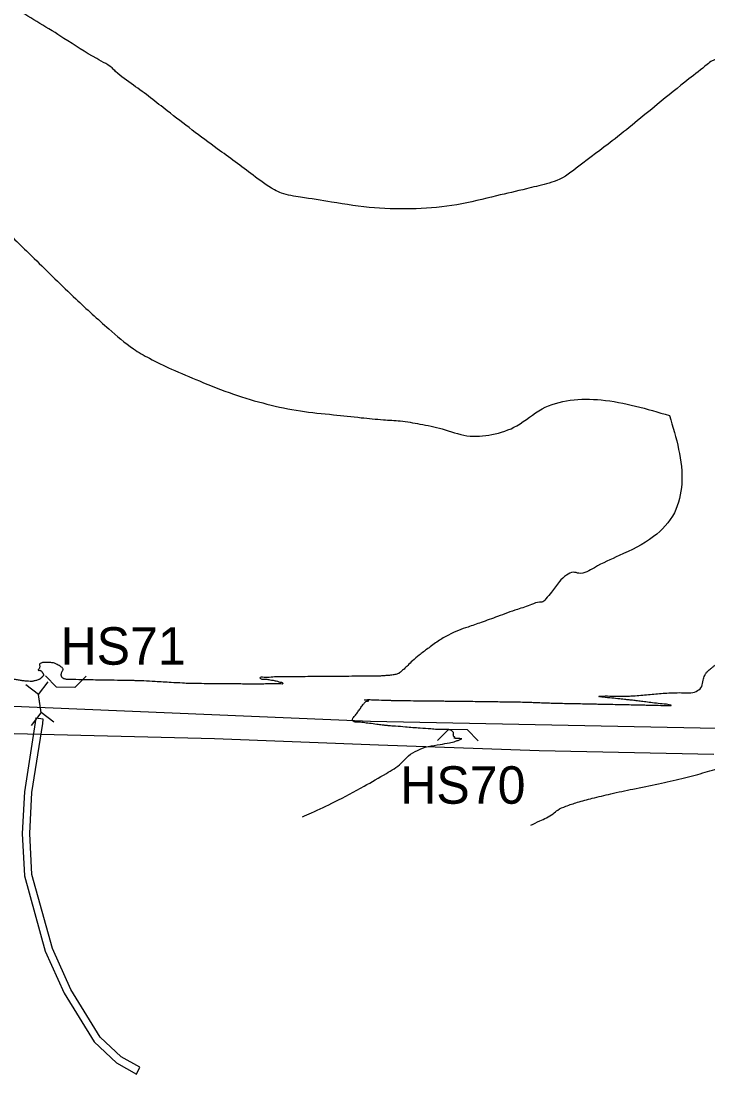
# Model space of a CAD drawing. Extents: x -478495 to -472450, y -1118050 to -1113745.
# Drawn here: x -477425.6 to -477242.5, y -1117514.1 to -1117227.6 of the extents above; entities that cross this region are included whole.
import ezdxf

# ---------------------------------------------------------------- set-up
doc = ezdxf.new("R2010")
doc.units = 0
for name, color, linetype in [('hospodářské sjezdy', 7, 'Continuous'), ('hranice kú', 7, 'Continuous'), ('ObPÚ', 7, 'Continuous'), ('silnice', 7, 'Continuous'), ('TP_MO', 7, 'Continuous'), ('vodní plochy', 7, 'Continuous'), ('Vrstevnice_hlavni', 7, 'Continuous'), ('Vrstevnice_vedlejsi', 7, 'Continuous')]:
    doc.layers.add(name, color=color, linetype=linetype)

msp = doc.modelspace()

# ---------------------------------------------------------------- linework, layer by layer
at = {"layer": 'hospodářské sjezdy'}
for p, q in [((-477416.22, -1117405.22), (-477419.21, -1117402.18)), ((-477408.29, -1117402.28), (-477411.33, -1117405.27)), ((-477411.33, -1117405.27), (-477416.22, -1117405.22)), ((-477314.62, -1117419.39), (-477311.57, -1117416.41)), ((-477311.57, -1117416.41), (-477306.68, -1117416.45)), ((-477306.68, -1117416.45), (-477303.7, -1117419.5))]:
    msp.add_line(p, q, dxfattribs=at)
at = {"layer": 'hranice kú'}
for p, q in [((-477427.56, -1117417.53), (-477374.08, -1117418.87)), ((-477374.08, -1117418.87), (-477330.37, -1117420.56)), ((-477330.37, -1117420.56), (-477287.49, -1117422.06)), ((-477287.49, -1117422.06), (-477240.82, -1117423.03))]:
    msp.add_line(p, q, dxfattribs=at)
at = {"layer": 'ObPÚ'}
for p, q in [((-477427.56, -1117417.53), (-477374.08, -1117418.87)), ((-477374.08, -1117418.87), (-477330.37, -1117420.56)), ((-477330.37, -1117420.56), (-477287.49, -1117422.06)), ((-477287.49, -1117422.06), (-477240.82, -1117423.03))]:
    msp.add_line(p, q, dxfattribs=at)
at = {"layer": 'silnice'}
msp.add_lwpolyline([(-478070.5, -1117514.11), (-478065.52, -1117512.47), (-477835.7, -1117440.29), (-477736.73, -1117410.08), (-477702.34, -1117405.05), (-477652.85, -1117401.69), (-477590.78, -1117403.37), (-477332.45, -1117414.28), (-477204.96, -1117416.8), (-477142.05, -1117416.8), (-477096.76, -1117410.08), (-477037.2, -1117399.17), (-476978.49, -1117379.03), (-476883.71, -1117344.63), (-476756.22, -1117298.47), (-476633.76, -1117254.83), (-476588.47, -1117242.24), (-476550.73, -1117234.69), (-476503.76, -1117230.5), (-476424.07, -1117228.82)], dxfattribs=at)
at = {"layer": 'TP_MO'}
for p, q in [((-477421.04, -1117407.15), (-477418.49, -1117403.73)), ((-477421.03, -1117407.15), (-477424.43, -1117404.57)), ((-477420.33, -1117411.98), (-477421.04, -1117407.15)), ((-477420.37, -1117411.99), (-477421.03, -1117407.15)), ((-477422.94, -1117415.39), (-477420.37, -1117411.99)), ((-477416.91, -1117414.53), (-477420.33, -1117411.98))]:
    msp.add_line(p, q, dxfattribs=at)
at = {"layer": 'vodní plochy'}
msp.add_line((-477419.79, -1117413.7), (-477421.79, -1117413.46), dxfattribs=at)
for points in [[(-477421.79, -1117413.46), (-477424.8, -1117433.08), (-477425.36, -1117444.25), (-477424.8, -1117455.48), (-477419.22, -1117475.59), (-477414.17, -1117486.79), (-477406.18, -1117499.83), (-477400.19, -1117505.4), (-477394.91, -1117508.4), (-477394.03, -1117506.59), (-477398.99, -1117503.77), (-477404.62, -1117498.55), (-477412.4, -1117485.85), (-477417.33, -1117474.91), (-477422.81, -1117455.16), (-477423.36, -1117444.25), (-477422.81, -1117433.29), (-477419.91, -1117414.9), (-477419.79, -1117413.7)], [(-477421.79, -1117413.46), (-477421.8, -1117413.5)]]:
    msp.add_lwpolyline(points, dxfattribs=at)
at = {"layer": 'Vrstevnice_hlavni'}
for points in [[(-477153.58, -1117330.61), (-477157.86, -1117323.6), (-477159.3, -1117321.25), (-477160.02, -1117320.05), (-477160.04, -1117320.02), (-477160.06, -1117319.99), (-477160.08, -1117319.95), (-477160.09, -1117319.92), (-477162.72, -1117315.47), (-477167.96, -1117306.59), (-477175.82, -1117293.29), (-477181.55, -1117283.11), (-477185.16, -1117276.05), (-477186.65, -1117272.1), (-477188.09, -1117266.33), (-477189.46, -1117258.76), (-477190.78, -1117249.38), (-477191.65, -1117242.24), (-477192.06, -1117237.32), (-477192.02, -1117234.65), (-477191.54, -1117229.31), (-477190.64, -1117221.32), (-477189.31, -1117210.66), (-477189.55, -1117199.31), (-477191.37, -1117187.28), (-477194.76, -1117174.57), (-477196.82, -1117165.88), (-477197.55, -1117161.23), (-477196.96, -1117160.61), (-477196.96, -1117159.86), (-477197.57, -1117158.97), (-477198.79, -1117157.95), (-477199.83, -1117157.38), (-477200.69, -1117157.26), (-477201.38, -1117157.59), (-477202.44, -1117158.04), (-477203.85, -1117158.62), (-477205.63, -1117159.31), (-477208.96, -1117161.25), (-477213.84, -1117164.43), (-477220.28, -1117168.85), (-477226.05, -1117172.54), (-477231.15, -1117175.49), (-477235.57, -1117177.7), (-477239.52, -1117180.2), (-477243, -1117182.99), (-477248.99, -1117189.15)], [(-477289.68, -1117442), (-477287.3, -1117440.86), (-477283.77, -1117438.99), (-477282.51, -1117437.97), (-477280.34, -1117436.94), (-477277.27, -1117435.89), (-477273.29, -1117434.82), (-477268.35, -1117433.64), (-477262.46, -1117432.35), (-477255.62, -1117430.94), (-477249.39, -1117429.51), (-477243.77, -1117428.06), (-477238.75, -1117426.58), (-477234.78, -1117425.57), (-477231.84, -1117425.04), (-477228.04, -1117424.94)]]:
    msp.add_spline(points, degree=3, dxfattribs=at)
at = {"layer": 'Vrstevnice_vedlejsi'}
for points in [[(-477011.01, -1117366.82), (-477013.49, -1117363.41), (-477017.82, -1117359.78), (-477023.98, -1117355.94), (-477031.99, -1117351.88), (-477040.4, -1117349.15), (-477049.21, -1117347.75), (-477058.41, -1117347.69), (-477065.93, -1117347.54), (-477071.75, -1117347.31), (-477075.87, -1117347), (-477082.92, -1117343.82), (-477092.9, -1117337.79), (-477105.8, -1117328.9), (-477114.55, -1117322.88), (-477119.14, -1117319.74), (-477119.57, -1117319.48), (-477122.39, -1117317.48), (-477127.6, -1117313.74), (-477135.2, -1117308.27), (-477141.72, -1117302.08), (-477147.16, -1117295.2), (-477151.51, -1117287.6), (-477154.62, -1117282.28), (-477156.48, -1117279.23), (-477157.09, -1117278.46), (-477157.75, -1117276.95), (-477158.46, -1117274.7), (-477159.23, -1117271.7), (-477160.62, -1117267.39), (-477162.62, -1117261.76), (-477165.24, -1117254.81), (-477167.11, -1117249.3), (-477168.23, -1117245.24), (-477168.6, -1117242.62), (-477168.79, -1117237.37), (-477168.8, -1117229.49), (-477168.64, -1117218.98), (-477168.41, -1117211.03), (-477168.12, -1117205.65), (-477167.77, -1117202.82), (-477167.83, -1117199.82), (-477168.31, -1117196.63), (-477169.21, -1117193.26), (-477168.69, -1117189.85), (-477166.74, -1117186.41), (-477163.38, -1117182.92), (-477160.08, -1117178.43), (-477156.85, -1117172.94), (-477153.69, -1117166.45), (-477148.19, -1117158.76), (-477140.35, -1117149.87), (-477130.18, -1117139.77), (-477122.85, -1117132.51), (-477118.38, -1117128.07), (-477116.76, -1117126.47), (-477114.7, -1117124.86), (-477112.2, -1117123.25), (-477109.27, -1117121.62), (-477108.83, -1117118.29), (-477110.89, -1117113.26), (-477115.45, -1117106.51), (-477120.43, -1117101.77), (-477125.83, -1117099.01), (-477131.67, -1117098.25), (-477138.05, -1117097.27), (-477145, -1117096.06), (-477152.5, -1117094.62), (-477159.77, -1117094.47), (-477166.81, -1117095.6), (-477173.62, -1117098.01), (-477180.33, -1117100.68), (-477186.95, -1117103.6), (-477193.48, -1117106.78), (-477198.48, -1117109.36), (-477201.97, -1117111.33), (-477203.95, -1117112.7), (-477206.84, -1117114.28), (-477210.65, -1117116.05), (-477215.37, -1117118.03), (-477220.02, -1117120.06), (-477224.58, -1117122.16), (-477229.06, -1117124.31), (-477232.76, -1117126.03), (-477235.69, -1117127.3), (-477237.85, -1117128.14), (-477243.61, -1117132.15), (-477252.98, -1117139.32), (-477265.95, -1117149.66), (-477274.72, -1117156.68), (-477279.29, -1117160.36), (-477279.64, -1117160.73), (-477283.16, -1117162.02), (-477289.83, -1117164.23), (-477299.66, -1117167.37), (-477307.39, -1117170.12), (-477313, -1117172.5)], [(-477242.82, -1117401.21), (-477242.33, -1117400.79), (-477241.8, -1117400.34), (-477241.23, -1117399.87), (-477240.61, -1117399.36), (-477236.99, -1117397.93), (-477230.35, -1117395.56), (-477220.69, -1117392.26), (-477213.03, -1117389.42), (-477207.36, -1117387.03), (-477203.68, -1117385.1), (-477198.77, -1117383.71), (-477192.62, -1117382.83), (-477185.23, -1117382.49), (-477180.36, -1117379.8), (-477178, -1117374.76), (-477178.16, -1117367.37), (-477179.95, -1117358.72), (-477183.39, -1117348.81), (-477188.47, -1117337.63), (-477192.24, -1117329.46), (-477194.73, -1117324.3), (-477195.91, -1117322.15), (-477197.02, -1117320.01), (-477198.06, -1117317.88), (-477199.03, -1117315.76), (-477201.83, -1117310.61), (-477206.45, -1117302.43), (-477212.91, -1117291.22), (-477218.99, -1117279.8), (-477224.71, -1117268.2), (-477230.05, -1117256.4), (-477233.79, -1117248.02), (-477235.92, -1117243.07), (-477236.45, -1117241.53), (-477237.13, -1117240.2), (-477237.98, -1117239.05), (-477238.99, -1117238.11), (-477240.1, -1117237.79), (-477241.31, -1117238.11), (-477242.62, -1117239.05), (-477247.5, -1117242.93), (-477255.95, -1117249.73), (-477267.98, -1117259.46), (-477276.91, -1117266.23), (-477282.75, -1117270.04), (-477285.5, -1117270.89), (-477290.86, -1117272.25), (-477298.83, -1117274.11), (-477309.42, -1117276.48), (-477320.28, -1117277.55), (-477331.42, -1117277.32), (-477342.84, -1117275.79), (-477351.1, -1117274.48), (-477356.18, -1117273.39), (-477358.09, -1117272.52), (-477363.81, -1117268.57), (-477373.33, -1117261.55), (-477386.67, -1117251.46), (-477395.71, -1117244.59), (-477400.46, -1117240.92), (-477400.92, -1117240.46), (-477405.52, -1117237.52), (-477414.25, -1117232.1), (-477427.13, -1117224.2), (-477436.8, -1117218.2), (-477443.26, -1117214.12), (-477446.52, -1117211.95), (-477449.73, -1117209.41), (-477452.89, -1117206.52), (-477456.01, -1117203.26), (-477459.05, -1117199.24), (-477461.99, -1117194.46), (-477464.85, -1117188.93), (-477466.73, -1117184.68), (-477467.64, -1117181.73), (-477467.56, -1117180.07), (-477467.63, -1117178.9), (-477467.83, -1117178.24), (-477468.17, -1117178.08), (-477468.45, -1117177.98), (-477468.66, -1117177.92), (-477468.82, -1117177.91), (-477468.77, -1117177.84), (-477468.54, -1117177.71), (-477468.11, -1117177.51), (-477467.67, -1117177.3), (-477467.24, -1117177.09), (-477466.8, -1117176.87), (-477466.1, -1117176.55), (-477465.15, -1117176.12), (-477463.93, -1117175.58), (-477461.97, -1117174.77), (-477459.28, -1117173.7), (-477455.84, -1117172.37), (-477453.29, -1117171.29), (-477451.6, -1117170.47)], [(-477490.07, -1117220.51), (-477485.04, -1117225.92), (-477481.21, -1117230.03), (-477478.59, -1117232.81), (-477477.18, -1117234.29), (-477475.53, -1117235.74), (-477473.65, -1117237.18), (-477471.53, -1117238.59), (-477468.39, -1117241.08), (-477464.23, -1117244.63), (-477459.06, -1117249.26), (-477454.07, -1117254.51), (-477449.26, -1117260.37), (-477444.63, -1117266.85), (-477440.8, -1117271.92), (-477437.78, -1117275.56), (-477435.56, -1117277.78), (-477430.37, -1117282.86), (-477422.22, -1117290.79), (-477411.11, -1117301.59), (-477402.28, -1117309.63), (-477395.72, -1117314.92), (-477391.45, -1117317.46), (-477385.58, -1117320.32), (-477378.11, -1117323.5), (-477369.06, -1117327), (-477360.08, -1117329.67), (-477351.17, -1117331.51), (-477342.34, -1117332.51), (-477334.96, -1117333.29), (-477329.01, -1117333.84), (-477324.51, -1117334.17), (-477319.29, -1117334.99), (-477313.36, -1117336.3), (-477306.73, -1117338.1), (-477300.07, -1117337.81), (-477293.4, -1117335.43), (-477286.7, -1117330.96), (-477279.2, -1117328.66), (-477270.91, -1117328.56), (-477252.72, -1117332.72)], [(-477252.72, -1117332.72), (-477249.44, -1117350.91), (-477251.4, -1117358.65), (-477256.95, -1117365.03), (-477266.11, -1117370.07), (-477272.73, -1117373.33), (-477276.84, -1117374.81), (-477278.42, -1117374.53), (-477280.16, -1117375.27), (-477282.07, -1117377.02), (-477284.14, -1117379.8), (-477285.71, -1117381.65), (-477286.78, -1117382.55), (-477287.36, -1117382.52), (-477289.51, -1117383.14), (-477293.25, -1117384.42), (-477298.57, -1117386.35), (-477302.97, -1117387.93), (-477306.45, -1117389.15), (-477309.02, -1117390.03), (-477311.67, -1117391.28), (-477314.39, -1117392.9), (-477317.2, -1117394.91), (-477319.49, -1117396.66), (-477321.26, -1117398.15), (-477322.52, -1117399.39), (-477323.52, -1117400.34), (-477324.25, -1117401.01), (-477324.72, -1117401.4), (-477325.45, -1117401.7), (-477326.46, -1117401.92), (-477327.73, -1117402.06), (-477328.93, -1117402.16), (-477330.08, -1117402.22), (-477331.16, -1117402.25), (-477332.75, -1117402.26), (-477334.85, -1117402.28), (-477337.47, -1117402.29), (-477340.6, -1117402.31), (-477344.24, -1117402.34), (-477348.39, -1117402.37), (-477351.46, -1117402.4), (-477353.46, -1117402.41), (-477354.37, -1117402.41), (-477355.07, -1117402.4), (-477355.56, -1117402.4), (-477355.84, -1117402.39), (-477356.81, -1117402.42), (-477358.48, -1117402.48), (-477360.84, -1117402.58), (-477361.95, -1117402.71), (-477361.81, -1117402.86), (-477360.42, -1117403.04), (-477359.31, -1117403.21), (-477358.47, -1117403.34), (-477357.91, -1117403.45), (-477357.29, -1117403.61), (-477356.62, -1117403.82), (-477355.89, -1117404.07), (-477355.82, -1117404.24), (-477356.4, -1117404.32), (-477357.64, -1117404.32), (-477359.15, -1117404.33), (-477360.93, -1117404.34), (-477362.99, -1117404.37), (-477364.62, -1117404.38), (-477365.83, -1117404.37), (-477366.62, -1117404.34), (-477368.47, -1117404.31), (-477371.39, -1117404.29), (-477375.37, -1117404.27), (-477378.26, -1117404.24), (-477380.04, -1117404.23), (-477380.72, -1117404.21), (-477382.6, -1117404.11), (-477385.67, -1117403.95), (-477389.92, -1117403.7), (-477392.94, -1117403.53), (-477394.73, -1117403.45), (-477395.27, -1117403.45), (-477395.83, -1117403.44), (-477396.42, -1117403.43), (-477397.03, -1117403.42), (-477399.11, -1117403.38), (-477402.66, -1117403.32), (-477407.67, -1117403.24), (-477411.11, -1117403.18), (-477412.96, -1117403.15), (-477413.23, -1117403.14), (-477413.48, -1117403.11), (-477413.73, -1117403.07), (-477413.97, -1117403.01), (-477414.17, -1117402.95), (-477414.34, -1117402.89), (-477414.49, -1117402.82), (-477414.61, -1117402.73), (-477414.71, -1117402.64)], [(-477414.71, -1117402.64), (-477414.79, -1117402.52), (-477414.86, -1117402.38), (-477414.92, -1117402.22), (-477414.96, -1117402.03), (-477414.97, -1117401.83), (-477414.94, -1117401.6), (-477414.87, -1117401.34), (-477414.78, -1117401.09), (-477414.66, -1117400.84), (-477414.51, -1117400.59), (-477414.5, -1117400.34), (-477414.63, -1117400.1), (-477414.89, -1117399.87), (-477415.27, -1117399.6), (-477415.77, -1117399.28), (-477416.39, -1117398.93), (-477417.22, -1117398.69), (-477418.27, -1117398.58), (-477419.54, -1117398.59), (-477420.37, -1117398.76), (-477420.76, -1117399.06), (-477420.72, -1117399.52), (-477420.75, -1117399.91), (-477420.86, -1117400.22), (-477421.06, -1117400.47), (-477421.1, -1117400.62), (-477420.98, -1117400.7), (-477420.7, -1117400.68), (-477420.48, -1117400.74), (-477420.31, -1117400.85), (-477420.19, -1117401.03), (-477420.07, -1117401.2), (-477419.94, -1117401.37), (-477419.81, -1117401.54), (-477419.72, -1117401.68), (-477419.67, -1117401.79), (-477419.67, -1117401.87), (-477419.67, -1117401.94), (-477419.68, -1117402.02), (-477419.71, -1117402.09), (-477419.74, -1117402.15), (-477419.79, -1117402.19), (-477419.84, -1117402.22), (-477419.95, -1117402.31), (-477420.1, -1117402.48), (-477420.31, -1117402.71), (-477420.47, -1117402.87), (-477420.58, -1117402.98), (-477420.65, -1117403.02), (-477420.84, -1117403.1), (-477421.15, -1117403.22), (-477421.58, -1117403.36), (-477421.99, -1117403.48), (-477422.36, -1117403.57), (-477422.71, -1117403.64), (-477423.28, -1117403.64), (-477424.08, -1117403.59), (-477425.1, -1117403.49), (-477426.14, -1117403.35), (-477427.19, -1117403.18), (-477428.26, -1117402.98), (-477429.22, -1117402.83), (-477430.07, -1117402.74), (-477430.81, -1117402.7), (-477432.26, -1117402.67), (-477434.44, -1117402.64), (-477437.32, -1117402.62), (-477439.63, -1117402.59), (-477441.35, -1117402.57), (-477442.49, -1117402.56), (-477443.83, -1117402.53), (-477445.38, -1117402.5), (-477447.13, -1117402.46), (-477448.68, -1117402.43), (-477450.02, -1117402.4), (-477451.15, -1117402.38), (-477452.06, -1117402.34), (-477452.74, -1117402.28), (-477453.19, -1117402.19), (-477453.75, -1117402.07), (-477454.41, -1117401.91), (-477455.18, -1117401.72), (-477455.75, -1117401.58), (-477456.12, -1117401.51), (-477456.29, -1117401.5), (-477456.69, -1117401.51), (-477457.31, -1117401.51), (-477458.16, -1117401.53), (-477459, -1117401.58), (-477459.82, -1117401.68), (-477460.62, -1117401.8), (-477461.42, -1117401.89), (-477462.21, -1117401.92), (-477462.99, -1117401.91), (-477464.19, -1117401.87), (-477465.81, -1117401.81)], [(-477327.9, -1117415.45), (-477328.37, -1117415.41), (-477329.34, -1117415.29), (-477330.8, -1117415.11), (-477332.76, -1117414.85), (-477334.42, -1117414.65), (-477335.76, -1117414.51), (-477336.79, -1117414.42), (-477337.25, -1117414.08), (-477337.14, -1117413.48), (-477336.46, -1117412.63), (-477335.8, -1117411.75), (-477335.16, -1117410.84), (-477334.55, -1117409.91), (-477333.98, -1117409.26), (-477333.47, -1117408.92), (-477333.01, -1117408.87), (-477332.95, -1117408.79), (-477333.31, -1117408.69), (-477334.07, -1117408.57), (-477333.69, -1117408.52), (-477332.18, -1117408.53), (-477329.52, -1117408.62), (-477327.68, -1117408.67), (-477326.65, -1117408.7), (-477326.43, -1117408.7), (-477325.12, -1117408.72), (-477322.71, -1117408.76), (-477319.2, -1117408.81), (-477316.7, -1117408.84), (-477315.21, -1117408.86), (-477314.73, -1117408.85), (-477314.19, -1117408.85), (-477313.57, -1117408.85), (-477312.89, -1117408.87), (-477311.36, -1117408.88), (-477308.98, -1117408.91), (-477305.77, -1117408.95), (-477303.3, -1117408.98), (-477301.57, -1117409), (-477300.59, -1117409.02), (-477299.03, -1117409.04), (-477296.89, -1117409.06), (-477294.18, -1117409.1), (-477291.92, -1117409.14), (-477290.11, -1117409.19), (-477288.74, -1117409.26), (-477287.25, -1117409.31), (-477285.62, -1117409.37), (-477283.85, -1117409.42), (-477281.83, -1117409.47), (-477279.54, -1117409.52), (-477276.99, -1117409.57), (-477274.79, -1117409.61), (-477272.94, -1117409.65), (-477271.44, -1117409.69), (-477269.54, -1117409.73), (-477267.23, -1117409.77), (-477264.53, -1117409.82), (-477262.43, -1117409.86), (-477260.95, -1117409.89), (-477260.07, -1117409.92), (-477258.52, -1117409.95), (-477256.29, -1117410.01), (-477253.38, -1117410.07), (-477252.22, -1117410.02), (-477252.82, -1117409.86), (-477255.18, -1117409.6), (-477257.25, -1117409.35), (-477259.03, -1117409.13), (-477260.51, -1117408.93), (-477261.89, -1117408.76), (-477263.17, -1117408.62), (-477264.33, -1117408.5), (-477265.97, -1117408.33), (-477268.08, -1117408.11), (-477270.66, -1117407.84), (-477271.52, -1117407.66), (-477270.65, -1117407.56), (-477268.07, -1117407.55), (-477266.16, -1117407.55), (-477264.93, -1117407.57), (-477264.39, -1117407.6), (-477263.36, -1117407.56), (-477261.84, -1117407.45), (-477259.82, -1117407.28), (-477257.83, -1117407.11), (-477255.86, -1117406.95), (-477253.91, -1117406.79), (-477251.78, -1117406.69), (-477249.47, -1117406.65), (-477246.97, -1117406.66), (-477245.18, -1117406.11), (-477244.09, -1117405), (-477243.7, -1117403.31), (-477243.27, -1117402.05), (-477242.82, -1117401.21)], [(-477350.65, -1117439.79), (-477348.22, -1117438.74), (-477342.04, -1117435.76), (-477334.15, -1117431.6), (-477328.23, -1117428.18), (-477324.29, -1117425.48), (-477322.34, -1117423.52), (-477319.94, -1117422.04), (-477317.12, -1117421.02), (-477313.86, -1117420.48), (-477311.41, -1117420), (-477309.76, -1117419.61), (-477308.91, -1117419.29), (-477308.36, -1117419.07), (-477308.09, -1117418.96), (-477308.12, -1117418.96), (-477308.38, -1117418.94), (-477308.88, -1117418.9), (-477309.6, -1117418.85), (-477310.03, -1117418.79), (-477310.16, -1117418.72), (-477309.98, -1117418.64), (-477309.93, -1117418.55), (-477310.01, -1117418.45), (-477310.21, -1117418.34), (-477310.33, -1117418.17), (-477310.37, -1117417.94), (-477310.34, -1117417.65), (-477310.34, -1117417.43), (-477310.36, -1117417.27), (-477310.42, -1117417.18), (-477310.5, -1117417.08), (-477310.61, -1117416.98), (-477310.75, -1117416.86), (-477310.89, -1117416.75), (-477311.01, -1117416.65), (-477311.12, -1117416.57), (-477311.44, -1117416.52), (-477311.96, -1117416.5), (-477312.69, -1117416.5), (-477313.38, -1117416.5), (-477314.04, -1117416.49), (-477314.66, -1117416.46), (-477316.39, -1117416.34), (-477319.22, -1117416.13), (-477323.15, -1117415.83), (-477325.79, -1117415.62), (-477327.13, -1117415.52), (-477327.17, -1117415.51), (-477327.23, -1117415.51), (-477327.29, -1117415.5), (-477327.36, -1117415.5), (-477327.56, -1117415.48), (-477327.9, -1117415.45)]]:
    msp.add_spline(points, degree=3, dxfattribs=at)

# ---------------------------------------------------------------- texts
at = {"layer": 'hospodářské sjezdy'}
for s, p in [('HS71', (-477415.2, -1117399.19)), ('HS70', (-477324.56, -1117436.28))]:
    msp.add_text(s, height=10, rotation=360, dxfattribs=at).set_placement(p)

doc.saveas('drawing.dxf')
